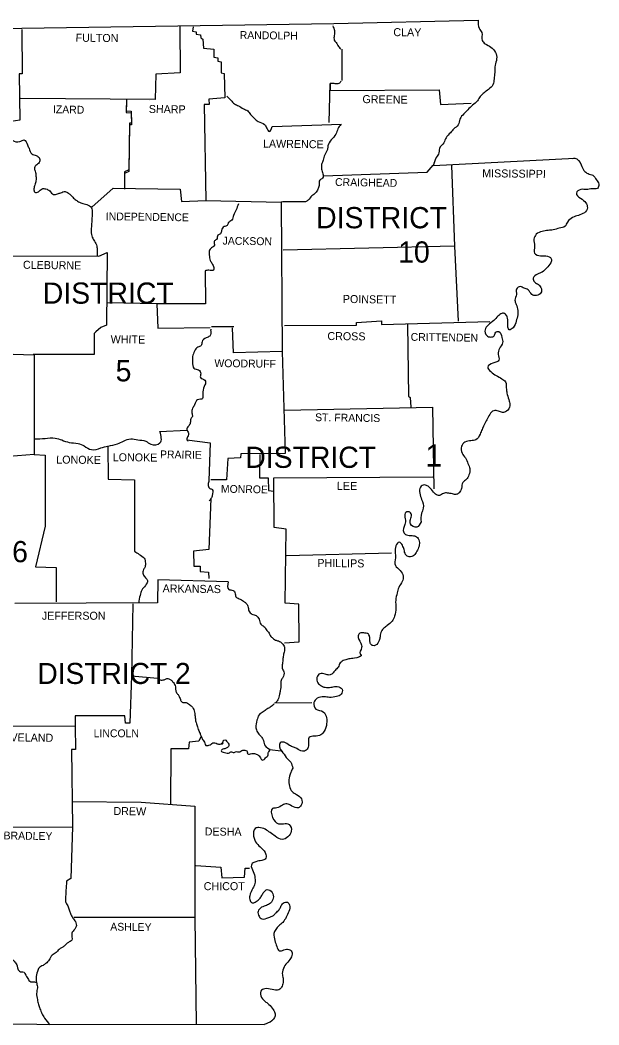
# Model space of a CAD drawing. Extents: x -17668 to 16999, y -17303 to 5867.
# Drawn here: x 2998 to 4708, y 2895 to 5867 of the extents above; entities that cross this region are included whole.
import ezdxf

# ---------------------------------------------------------------- set-up
doc = ezdxf.new("R2010")
doc.units = 0
for name, color, linetype in [('1', 7, 'Continuous'), ('2', 7, 'Continuous'), ('3', 7, 'Continuous')]:
    doc.layers.add(name, color=color, linetype=linetype)

msp = doc.modelspace()

# ---------------------------------------------------------------- linework, layer by layer
at = {"layer": '1'}
for p, q in [((4219.3, 5436.9), (4225.9, 5457.3)), ((4221, 5443.5), (4227.6, 5459.5)), ((3563.3, 4960.3), (3628.8, 4960.3)), ((3749.3, 3847.5), (3859.4, 3849.1))]:
    msp.add_line(p, q, dxfattribs=at)
for points in [[(1332.2, 5841.4), (2222.1, 5840.9), (3003, 5842.5), (3924.3, 5856.8), (4351.4, 5866.7)], [(3003, 5839.2), (3004.1, 5708.2), (2994.8, 5707.7), (2996.4, 5570.7), (2957.9, 5565.2), (2961.2, 5528.3), (2974.4, 5511.2), (2973.3, 5467.7), (2898.5, 5465), (2895.7, 5397.8), (2827.5, 5395.6), (2824.2, 5314.2), (2828, 5307.6), (2829.7, 5177.7), (2947.5, 5170), (2945.8, 4880), (3039.4, 4877.2), (3039.4, 4582.2), (2965.6, 4576.7), (2960.1, 4511.8), (2836.3, 4511.2)], [(3469.2, 5847.5), (3470.3, 5711), (3398.7, 5707.1), (3396.5, 5632.3), (2998.6, 5634.5)], [(3508.8, 5846.9), (3507.2, 5833.7), (3518.2, 5832.1), (3517.6, 5825.5), (3530.3, 5822.7), (3531.4, 5813.9), (3537.4, 5810.1), (3539.1, 5783.6), (3570.5, 5780.3), (3570.5, 5756.7), (3582, 5755), (3582, 5745.7), (3591.9, 5742.9), (3591.4, 5711), (3600.2, 5709.3), (3602.4, 5637.2), (3555.6, 5632.8), (3556.1, 5617.4), (3541.8, 5616.9), (3546.8, 5332.9), (3768.6, 5327.9), (3772.4, 4886.6), (3627.7, 4882.7), (3624.9, 4957)], [(3948.5, 5780.9), (3948.5, 5687.9)], [(3911.1, 5564.1), (3913.9, 5679.1), (3913.9, 5658.7), (4235.8, 5660.4), (4240.2, 5617.4), (4331, 5620.7)], [(3311.8, 5630.6), (3310.7, 5598.7), (3326.1, 5597.6), (3326.6, 5562.4), (3321.1, 5562.4), (3318.9, 5423.7), (3306.3, 5418.2), (3306.3, 5372)], [(3311.8, 5625.7), (3310.7, 5593.8), (3326.1, 5592.7), (3326.6, 5557.4), (3321.1, 5557.4), (3318.9, 5418.8), (3306.3, 5413.3), (3306.3, 5367)], [(3380.6, 5629.5), (3381.1, 5630.1)], [(3742.7, 5551.9), (3946.9, 5559.1)], [(4219.3, 5436.9), (4637, 5458.4)], [(3894.6, 5406.7), (4200.1, 5416.6), (4218.2, 5437.5)], [(4272.2, 5436.4), (4281.5, 5198.1), (4292.5, 4976.3)], [(3209.4, 5313.1), (3272.2, 5369.8), (3470.3, 5367), (3474.1, 5330.2), (3546.2, 5332.9)], [(3840.7, 5329.1), (3773.5, 5329.1), (3768.6, 5327.9)], [(2947.5, 5170), (3230.3, 5168.3), (3254.6, 5179.9), (3252.9, 4964.7), (3236.4, 4957.6), (3221.5, 4944.9), (3216.6, 4940), (3216, 4878.3), (3036.1, 4878.3)], [(4281.5, 5198.1), (3774.6, 5186.5)], [(3544, 5124.9), (3545.1, 5028), (3402, 5027.5), (3255.1, 5030.2)], [(3402, 5027.5), (3404.2, 4955.4), (3558.9, 4958.1)], [(3779, 4963.6), (3991.5, 4964.7), (3992, 4972.4), (4065.8, 4977.9), (4065.8, 4966.4), (4386.1, 4975.2)], [(4142.8, 4966.4), (4145.6, 4754.5), (4150.5, 4751.2), (4152.2, 4722.6)], [(3563.3, 4951), (3560.5, 4950.4)], [(3772.4, 4886.6), (3780.7, 4585), (3649.7, 4584.4), (3649.2, 4572.3), (3611.2, 4570.1), (3607.9, 4507.4), (3561.6, 4507.4)], [(3779, 4713.2), (4216, 4722)], [(4216, 4722), (4220.4, 4481)], [(3410.9, 4650.5), (3490.7, 4654.3)], [(3256.8, 4607.5), (3257.9, 4509), (3335.5, 4507.4), (3336, 4296)], [(3490.7, 4625.7), (3559.4, 4616.9), (3555.6, 4504.6)], [(3039.4, 4582.2), (3071.3, 4580), (3071.8, 4369.8), (3043.2, 4250.4), (3104.3, 4247.6), (3103.8, 4146.3)], [(3705.8, 4581.7), (3705.3, 4513.4), (3730.6, 4513.4), (3731.7, 4475.5), (3747.7, 4473.8)], [(3779, 4025.3), (3822, 4028), (3821.4, 4139.7), (3781.2, 4142.5), (3783.4, 4361), (3748.8, 4365.9), (3747.7, 4512.9), (4217.1, 4516.2)], [(3561.6, 4451.8), (3555, 4301), (3509.9, 4296), (3511, 4251.5), (3529.2, 4252), (3529.7, 4236.6), (3554.5, 4233.8), (3555, 4215.7)], [(3784.5, 4283.4), (4094.9, 4291.1)], [(3612.3, 4205.8), (3404.2, 4211.3), (3403.1, 4143.6), (2982.1, 4141.9)], [(3331, 4140.3), (3326.6, 3927.3), (3403.1, 3921.2)], [(3326.6, 3927.3), (3321.7, 3787.5), (3309, 3787.5), (3306.8, 3809), (3160.4, 3809), (3160.4, 3778.2)], [(2964.5, 3779.8), (3159.3, 3778.7)], [(3160.4, 3778.7), (3161, 3709.9), (3149.4, 3709.4), (3152.7, 3481)], [(3532.5, 3749.5), (3525.9, 3734.7), (3496.7, 3731.9), (3495.1, 3712.1), (3442.8, 3712.1), (3442.2, 3547.6)], [(3594.1, 3725.3), (3595.8, 3727), (3597.4, 3728.6), (3597.4, 3728.6)], [(3151.1, 3555.8), (3355.3, 3554.2), (3513.8, 3542.1)], [(3513.8, 3542.1), (3513.8, 3212.9), (3518.2, 2896.5)], [(2904, 3480.4), (3152.7, 3481)], [(3152.7, 3481), (3147.2, 3328), (3135.1, 3320.3)], [(3516.5, 3366.5), (3590.3, 3362.1), (3593.6, 3330.2), (3660.2, 3332.4), (3662.9, 3359.3), (3675.6, 3359.3)], [(1700.9, 3345), (1702, 2899.8), (3719, 2896.5)], [(3156, 3213.5), (3513.8, 3213.5)]]:
    msp.add_lwpolyline(points, dxfattribs=at)
for points in [[(4351.4, 5866.7), (4354.2, 5842.5), (4361.9, 5829.9), (4363, 5806.8), (4372.3, 5796.9), (4388.3, 5786.9), (4402.6, 5771), (4405.9, 5752.3), (4401.5, 5733), (4400.4, 5711.5), (4398.2, 5692.8), (4394.9, 5675.8), (4381.7, 5662), (4369, 5652.1), (4357.5, 5640.6), (4349.2, 5628.4), (4334.9, 5615.2), (4320.6, 5601.5), (4309, 5589.4), (4297.5, 5574), (4292, 5556.9), (4279.3, 5544.8), (4269.4, 5533.8), (4256.2, 5518.9), (4249.6, 5504.1), (4236.9, 5487), (4234.2, 5470.5), (4225.9, 5457.3), (4225.4, 5455.1)], [(3921.6, 5849.7), (3926.5, 5835.9), (3926, 5821.1), (3926, 5807.3), (3933.1, 5798), (3940.3, 5786.4), (3945.8, 5781.4)], [(3946.3, 5686.2), (3939.2, 5679.1), (3925.4, 5679.1), (3913.9, 5679.1)], [(3608.4, 5642.2), (3620.5, 5629.5), (3631, 5619.1), (3643.1, 5613), (3657.4, 5604.8), (3670.1, 5598.2), (3678.3, 5587.7), (3689.9, 5576.2), (3701.4, 5566.8), (3719.6, 5558), (3725.7, 5548.6), (3733.9, 5537.1), (3742.7, 5551.9)], [(3945.2, 5558.5), (3937, 5545.3), (3930.4, 5529.9), (3917.2, 5512.3), (3907.3, 5495.3), (3905.6, 5483.7), (3897.9, 5468.3), (3893.5, 5452.9), (3888.6, 5439.7), (3888.6, 5425.9), (3892.4, 5412.2), (3891.3, 5399.5), (3883.1, 5393.4), (3880.9, 5377.5), (3877.6, 5366.5), (3870.4, 5355.5), (3859.9, 5347.2), (3848.9, 5334.6), (3840.7, 5329.1)], [(2974.4, 5511.2), (2996.4, 5507.4), (3009.6, 5512.3), (3019, 5498), (3024, 5487), (3032.2, 5471), (3045.4, 5466.1), (3055.3, 5457.3), (3055.3, 5447.9), (3046.5, 5439.1), (3039.9, 5430.3), (3042.1, 5419.9), (3044.3, 5405.5), (3044.3, 5391.8), (3041, 5379.1), (3038.3, 5367.6), (3041, 5357.7), (3051.5, 5359.3), (3062.5, 5367.6), (3074, 5367.6), (3085, 5361.5), (3096.6, 5351.1), (3108.2, 5353.3), (3117.5, 5356), (3130.7, 5359.9), (3140.1, 5354.9), (3148.3, 5348.3), (3158.2, 5337.9), (3167.6, 5331.3), (3179.7, 5325.2), (3194.6, 5321.3), (3208.3, 5312), (3210.5, 5296), (3210, 5282.3), (3208.9, 5265.2), (3207.8, 5246.5), (3209.4, 5228.3), (3215.5, 5216.2), (3223.2, 5201.9), (3225.4, 5188.7), (3224.8, 5167.8)], [(4631, 5457.8), (4637, 5458.4), (4655.8, 5438.6), (4664, 5422.1), (4676.1, 5412.7), (4689.9, 5407.8), (4700.3, 5395.1), (4707.5, 5381.3), (4703.6, 5369.2), (4688.2, 5368.1), (4671.2, 5365.4), (4654.7, 5365.9), (4641.4, 5354.9), (4653.5, 5340.1), (4669.5, 5326.3), (4673.9, 5311.4), (4665.1, 5297.1), (4647.5, 5289.4), (4630.4, 5282.8), (4615, 5269.6), (4607.9, 5257), (4590.8, 5251.5), (4573.2, 5246.5), (4557.8, 5244.8), (4540.2, 5241.5), (4523.1, 5233.3), (4516, 5219), (4518.2, 5198.6), (4517.6, 5177.2), (4535.8, 5170), (4551.7, 5169.4), (4567.1, 5161.2), (4565.5, 5149.1), (4553.9, 5133.7), (4540.2, 5121.6), (4526.4, 5115.5), (4513.8, 5104), (4518.2, 5092.4), (4529.7, 5084.7), (4538, 5072), (4536.9, 5060.5), (4523.7, 5052.2), (4509.4, 5055.5), (4498.9, 5069.3), (4486.8, 5073.7), (4476.3, 5078.6), (4464.2, 5071.5), (4464.2, 5055.5), (4459.8, 5038.5), (4463.7, 5025.8), (4468.6, 5008.2), (4468.1, 4995), (4463.7, 4976.3), (4454.3, 4957), (4443.3, 4951), (4438.9, 4971.9), (4436.7, 4988.9), (4430.1, 4998.8), (4421.3, 4999.4), (4409.7, 4991.1), (4397.1, 4978.5), (4381.1, 4964.7), (4371.8, 4951), (4376.7, 4933.9), (4388.8, 4929.5), (4398.2, 4932.8), (4403.1, 4943.8), (4412.5, 4945.5), (4421.3, 4928.4)], [(3642.5, 5323), (3635.9, 5305.9), (3628.2, 5289.4), (3623.3, 5275.1), (3612.8, 5266.9), (3609.5, 5259.2), (3600.2, 5255.9), (3593, 5244.8), (3589.7, 5234.9), (3582, 5230.5), (3578.2, 5218.4), (3571, 5211.8), (3571.6, 5200.8), (3563.3, 5193.1), (3556.7, 5184.3), (3556.7, 5172.2), (3559.4, 5156.2), (3564.9, 5146.9), (3569.9, 5134.8), (3569.4, 5127.1), (3555.6, 5127.1), (3544, 5124.9)], [(3560.5, 4950.4), (3557.8, 4932.2), (3547.3, 4927.3), (3535.2, 4915.2), (3532.5, 4904.2), (3522.6, 4899.8), (3513.2, 4888.2), (3507.2, 4872.3), (3507.2, 4855.7), (3511, 4837), (3524.8, 4832.1), (3531.4, 4821.1), (3530.3, 4809.5), (3543.5, 4801.8), (3545.7, 4795.2), (3543.5, 4788.1), (3537.4, 4767.7), (3538, 4753.9), (3536.9, 4747.9), (3522, 4744), (3513.2, 4729.2), (3507.2, 4718.7), (3505, 4704.9), (3506.6, 4695), (3502.2, 4687.3), (3500.6, 4675.8), (3495.1, 4665.9), (3490.1, 4656.5), (3495.6, 4645.5), (3494, 4637.8), (3490.7, 4625.7), (3493.4, 4621.8)], [(4421.3, 4928.4), (4423.5, 4912.4), (4414.1, 4895.4), (4410.8, 4878.3), (4412.5, 4861.2), (4394.9, 4851.9), (4379.5, 4840.9), (4388.3, 4827.7), (4404.8, 4815.6), (4421.3, 4806.2), (4431.8, 4796.9), (4434.5, 4774.3), (4437.3, 4760), (4442.8, 4740.2), (4445, 4726.4), (4435.1, 4709.9), (4423.5, 4706.6), (4411.4, 4710.5), (4397.1, 4711.6), (4385.5, 4700.5), (4377.3, 4685.1), (4369, 4669.7), (4363, 4656.5), (4356.9, 4642.2), (4344.8, 4625.7), (4329.9, 4622.9), (4312.3, 4618.5), (4301.9, 4606.4), (4303.5, 4586.1), (4313.4, 4572.3), (4321.1, 4555.3), (4326.6, 4540.4), (4323.9, 4521.7), (4316.2, 4507.9), (4306.3, 4499.7), (4301.9, 4482.1), (4294.7, 4468.8), (4288.1, 4464.4), (4274.9, 4465.5), (4260.6, 4468.3), (4248.5, 4467.2), (4236.9, 4461.1), (4225.4, 4465), (4213.3, 4478.2), (4203.4, 4488.1), (4192.4, 4492), (4180.8, 4485.9), (4178.6, 4467.7), (4184.1, 4449), (4189.1, 4423.7), (4184.1, 4408.3), (4182.4, 4383)], [(3040.5, 4628.5), (3071.3, 4629.6), (3101.6, 4630.7), (3120.8, 4625.1), (3142.8, 4618), (3168.7, 4614.7), (3186.9, 4607.5), (3208.3, 4596.5), (3235.8, 4601.5), (3257.3, 4607), (3285.4, 4614.1), (3303.5, 4621.8), (3324.4, 4628.5), (3345.4, 4625.7), (3369, 4621.3), (3383.9, 4612.5), (3410.9, 4616.3), (3410.9, 4650.5)], [(3555.6, 4504.6), (3553.4, 4493.6), (3557.8, 4482.1), (3565.5, 4478.2), (3566.6, 4467.2), (3563.8, 4456.2), (3561.6, 4451.8), (3556.7, 4445.2)], [(4182.4, 4383), (4169.8, 4367), (4151.1, 4376.9), (4151.1, 4390.1), (4153.8, 4403.9), (4147.2, 4412.7), (4135.7, 4408.9), (4135.7, 4391.8), (4134.6, 4375.3), (4131.3, 4351.6), (4139, 4344.5), (4156.6, 4342.3), (4169.2, 4339), (4176.9, 4326.3), (4176.4, 4310.9), (4170.3, 4296), (4161.5, 4283.9), (4147.8, 4279.5), (4136.8, 4286.7), (4132.4, 4301), (4127.4, 4313.6), (4118.1, 4323), (4108.1, 4312.5), (4105.9, 4293.3), (4106.5, 4276.8), (4106.5, 4254.2), (4120.8, 4239.3), (4129.6, 4222.3), (4126.9, 4206.9), (4116.4, 4188.7), (4112, 4172.8), (4107.6, 4151.3), (4108.1, 4127.6), (4104.3, 4104.5), (4096.6, 4089.1), (4082.3, 4076.4), (4072.9, 4068.2), (4065.2, 4059.9), (4061.4, 4043.4), (4058.6, 4031.9), (4048.2, 4018.1), (4039.9, 4017), (4033.3, 4022.5), (4031.1, 4031.9), (4031.1, 4041.2), (4026.7, 4050.6), (4012.9, 4054.4), (4001.9, 4053.9), (3997, 4046.2), (4004.1, 4024.7), (4006.9, 4011), (4003, 3992.2), (4005.2, 3990), (3985.4, 3979.6), (3969.5, 3977.9), (3956.3, 3974.1), (3943.6, 3965.8), (3937.5, 3953.7), (3928.7, 3943.8), (3921, 3934.5), (3910.6, 3930.1), (3899, 3932.3), (3883.6, 3933.9), (3874.8, 3922.9), (3877.6, 3906.9), (3888, 3897.6), (3903.4, 3893.2), (3919.4, 3894.3), (3934.8, 3895.9), (3949.1, 3888.2), (3946.3, 3873.4), (3932.6, 3866.2), (3912.2, 3864), (3895.7, 3865.7), (3875.9, 3861.3), (3866, 3848.6), (3871.5, 3829.3), (3893, 3821.6), (3902.9, 3803.5), (3903.4, 3786.4), (3896.3, 3763.8), (3886.4, 3753.4), (3867.1, 3749), (3852.2, 3746.2), (3850, 3720.9), (3843.4, 3708.3), (3831.9, 3704.4), (3815.4, 3712.7), (3805.5, 3716.5), (3793.3, 3722), (3777.9, 3731.4), (3766.4, 3729.7), (3769.7, 3705.5), (3770.8, 3704.4), (3784, 3686.2), (3797.2, 3671.9), (3803.3, 3654.9)], [(3336, 4296), (3349.8, 4286.7), (3364.1, 4275.7), (3367.9, 4260.8), (3366.8, 4250.4), (3362.4, 4241.6), (3361.3, 4227.8), (3367.9, 4217.9), (3374, 4209.6), (3367.9, 4194.8), (3357.5, 4181), (3352, 4165.6), (3348.1, 4142.5)], [(3612.3, 4205.8), (3613.9, 4183.2), (3627.1, 4179.9), (3632.6, 4173.9), (3635.4, 4161.2), (3644.8, 4155.7), (3657.4, 4148), (3665.1, 4142.5), (3670.6, 4133.7), (3673.9, 4119.4), (3682.7, 4110), (3694.8, 4105.6), (3703.6, 4095.2), (3709.1, 4080.3), (3717.9, 4073.7), (3726.8, 4062.1), (3731.2, 4057.2), (3738.9, 4044), (3746.6, 4037.4), (3752.1, 4033.5), (3760.9, 4030.8), (3771.9, 4023.6), (3779, 4012.6), (3779, 4004.3), (3776.3, 3991.7), (3774.1, 3978.5), (3773, 3963.6), (3771.9, 3950.4), (3776.8, 3939.4), (3774.1, 3922.9), (3768.6, 3914.1), (3768, 3902), (3766.4, 3883.8), (3764.2, 3873.4), (3759.2, 3856.3), (3752.1, 3847.5)], [(3403.1, 3921.2), (3411.4, 3915.7), (3423, 3916.3), (3430.7, 3919.6), (3436.7, 3919), (3445, 3914.1), (3450.5, 3907.5), (3454.3, 3902.5), (3457.1, 3894.8), (3457.1, 3887.7), (3459.8, 3877.8), (3463.1, 3873.9), (3467.5, 3866.8), (3470.3, 3860.2), (3471.9, 3855.8), (3478, 3848.6), (3483.5, 3849.1), (3488.5, 3848.6), (3495.1, 3844.7), (3505, 3837), (3506.6, 3834.8), (3513.2, 3820.5), (3514.3, 3811.7), (3515.4, 3800.2), (3517.6, 3789.2), (3522, 3777.1), (3524.2, 3768.8), (3529.2, 3757.2), (3532.5, 3749.5), (3536.9, 3739.6), (3543.5, 3728.6), (3546.2, 3722), (3555.6, 3722.6), (3562.2, 3725.3), (3567.2, 3729.7), (3573.2, 3729.2), (3579.8, 3727), (3588.6, 3725.3), (3594.1, 3728.6), (3596.9, 3730.8), (3597.4, 3735.8), (3602.4, 3738.5), (3607.9, 3734.7), (3613.9, 3725.9), (3613.9, 3720.4), (3611.7, 3717.1), (3604.6, 3712.7), (3594.7, 3709.4), (3591.9, 3705.5), (3601.3, 3701.1), (3616.1, 3700), (3620, 3703.3), (3629.9, 3700.6), (3633.7, 3703.3), (3647, 3702.8), (3653, 3707.2), (3665.1, 3706.6), (3669, 3703.9), (3669, 3698.9), (3678.9, 3696.7), (3686, 3698.4), (3695.4, 3695.6), (3703.6, 3691.2), (3708, 3685.1), (3713.5, 3678.5), (3718.5, 3680.2), (3722.4, 3685.1), (3730.6, 3693.9), (3730.6, 3699.5), (3732.8, 3703.3), (3735.6, 3708.8)], [(3748.2, 3844.2), (3736.7, 3834.8), (3726.8, 3829.3), (3716.3, 3821.6), (3703.6, 3812.3), (3697.6, 3796.3), (3694.3, 3774.3), (3698.7, 3761.1), (3708.6, 3749.5), (3715.2, 3740.2), (3720.1, 3723.7), (3732.3, 3712.1), (3736.1, 3710.5)], [(3803.3, 3654.9), (3797.7, 3642.2), (3791.7, 3620.2), (3793.3, 3601.5), (3801.6, 3585.5), (3814.8, 3576.7), (3829.1, 3564.1), (3828, 3544.8), (3819.8, 3537.6), (3800.5, 3542.6), (3785.6, 3549.2), (3773, 3545.4), (3755.9, 3537.1), (3743.3, 3535.4), (3743.8, 3509), (3760.9, 3490.3), (3775.7, 3490.3), (3792.8, 3488.1), (3798.9, 3468.3), (3788.9, 3451.8), (3772.4, 3443.5), (3751.5, 3453.4), (3736.7, 3463.9), (3721.8, 3473.8), (3703.1, 3478.8), (3692.6, 3476.6), (3687.7, 3453.4), (3696.5, 3432.5), (3710.8, 3418.2), (3724, 3399.5), (3721.8, 3385.8), (3711.9, 3381.9), (3694.3, 3378), (3683.8, 3372.5), (3681.1, 3368.1), (3686.6, 3349.4), (3691.5, 3329.1), (3691.5, 3313.7), (3685.5, 3299.3), (3676.1, 3277.3), (3677.2, 3263), (3683.8, 3256.4), (3692.1, 3258.6), (3703.1, 3266.3), (3710.2, 3275.1), (3716.3, 3286.1), (3727.9, 3295.5), (3742.2, 3287.2), (3745.5, 3270.2), (3737.2, 3255.3), (3725.7, 3248.7), (3711.3, 3243.2), (3700.9, 3231.1), (3703.6, 3216.8), (3711.9, 3209.1), (3732.3, 3212.9), (3746, 3219), (3753.7, 3226.7), (3763.1, 3236.1), (3768, 3245.4), (3775.2, 3255.3), (3787.8, 3258.1), (3793.9, 3249.8), (3791.7, 3231.1), (3784, 3213.5), (3773.5, 3198.6), (3762, 3188.2), (3747.7, 3165.6), (3750.4, 3144.7), (3755.9, 3127.6), (3763.6, 3114.4), (3776.8, 3117.2), (3791.7, 3118.8), (3800.5, 3111.7), (3799.4, 3096.3), (3788.4, 3081.4), (3777.9, 3067.1), (3772.4, 3047.3), (3774.6, 3033.5), (3774.6, 3020.9), (3770.2, 3007.1), (3762.5, 2999.4), (3742.2, 3000), (3720.7, 3002.2), (3709.1, 2995.6), (3711.3, 2976.8), (3724, 2963.1), (3732.8, 2955.9), (3745.5, 2940.5), (3751, 2927.9), (3749.3, 2916.8), (3741.6, 2907.5), (3719, 2896.5)], [(3135.1, 3320.3), (3133.5, 3303.2), (3132.9, 3287.2), (3131.8, 3271.8), (3131.8, 3260.3), (3138.4, 3247.6), (3142.3, 3235.5), (3146.1, 3225), (3153.8, 3211.3), (3161, 3200.8), (3163.2, 3186), (3158.8, 3178.3), (3150.5, 3166.7), (3150, 3145.8), (3140.1, 3139.2), (3127.4, 3128.2), (3120.3, 3123.2), (3112.6, 3118.3), (3104.3, 3109.5), (3092.2, 3101.2), (3083.4, 3087.5), (3073.5, 3077), (3065.2, 3071.5), (3053.7, 3064.3), (3048.7, 3053.3), (3044.9, 3033), (3046.5, 3018.1), (3048.7, 3004.9), (3046, 2988.4), (3048.7, 2970.2), (3051.5, 2955.9), (3055.9, 2943.3), (3061.9, 2929), (3069.6, 2915.7), (3086.1, 2895.4)], [(2586.4, 3193.1), (2595.2, 3199.2), (2603.5, 3202.5), (2611.7, 3200.8), (2620.5, 3199.7), (2628.2, 3200.8), (2638.2, 3199.2), (2646.4, 3194.2), (2655.8, 3190.4), (2665.1, 3190.4), (2673.4, 3190.4), (2680.5, 3185.4), (2693.7, 3186), (2704.7, 3190.4), (2715.8, 3193.7), (2730.6, 3195.3), (2743.8, 3186), (2753.2, 3178.3), (2760.9, 3169.5), (2766.4, 3159.6), (2772.4, 3154.1), (2782.3, 3150.2), (2790.1, 3148.5), (2799.4, 3145.8), (2804.4, 3143.6), (2808.8, 3133.1), (2815.9, 3118.8), (2829.7, 3113.9), (2846.7, 3120.5), (2860.5, 3124.3), (2870.4, 3127.6), (2876.5, 3129.8), (2882, 3130.4), (2880.3, 3131.5), (2886.9, 3133.1), (2893, 3128.7), (2896.8, 3122.7), (2903.4, 3113.9), (2909.5, 3106.2), (2915.5, 3103.4), (2921.6, 3106.7), (2929.8, 3104), (2937, 3101.2), (2945.3, 3099), (2952.4, 3098.5), (2961.8, 3096.3), (2968.9, 3092.4), (2975.5, 3088.6), (2982.1, 3081.4), (2988.7, 3070.4), (2990.9, 3061.6), (2998.6, 3052.8), (3005.8, 3052.8), (3016.2, 3038.5), (3020.1, 3033), (3028.4, 3023.1), (3034.4, 3023.1), (3046, 3020.9)]]:
    msp.add_spline(points, degree=3, dxfattribs=at)
at = {"layer": '3'}
msp.add_line((3734.5, 3709.9), (3769.1, 3705.5), dxfattribs=at)

# ---------------------------------------------------------------- texts
at = {"layer": '1'}
msp.add_text('1', height=66, dxfattribs=at).set_placement((4195.7, 4546.4))
at = {"layer": '2'}
for s, height, rotation, p in [('FULTON', 23.66, 359.4996, (3161.5, 5802.9)), ('RANDOLPH', 23.11, 359.2583, (3646.4, 5811.2)), ('CLAY', 23.66, 359.2258, (4100.4, 5819.4)), ('SHARP', 23.66, 359.3905, (3377.8, 5592.1)), ('GREENE', 23.67, 359.2361, (4009.1, 5621.3)), ('IZARD', 23.11, 358.9258, (3094.4, 5591.6)), ('LAWRENCE', 23.67, 359.2678, (3715.2, 5489.8)), ('MISSISSIPPI', 23.66, 359.3097, (4363, 5402.2)), ('CRAIGHEAD', 23.11, 359.1159, (3928.2, 5376.4)), ('INDEPENDENCE', 23.108, 359.2187, (3250.7, 5275.1)), ('JACKSON', 23.11, 359.1352, (3595.8, 5203)), ('CLEBURNE', 23.66, 359.2535, (3005.8, 5131.5)), ('POINSETT', 23.66, 359.1987, (3951.1, 5030.4)), ('WHITE', 23.67, 359.3139, (3265, 4911.3)), ('CROSS', 23.66, 359.3839, (3905.6, 4920.7)), ('CRITTENDEN', 23.11, 359.213, (4151.6, 4918.5)), ('WOODRUFF', 23.11, 359.2748, (3571.6, 4840.9)), ('ST. FRANCIS', 23.108, 359.2216, (3869.3, 4680.7)), ('LONOKE', 23.67, 359.4974, (3104.3, 4555.3)), ('LONOKE', 23.67, 359.4974, (3271.1, 4562.4)), ('PRAIRIE', 23.11, 359.2116, (3410.9, 4571.2)), ('MONROE', 23.11, 359.0331, (3590.8, 4469.4)), ('LEE', 23.67, 359.4327, (3933.7, 4477.7)), ('PHILLIPS', 23.66, 359.3179, (3875.9, 4249.8)), ('ARKANSAS', 23.66, 359.2678, (3418.6, 4174.4)), ('CLEVELAND', 23.67, 359.3377, (2907.3, 3734.7)), ('DREW', 23.66, 359.2258, (3273.3, 3516.2)), ('DESHA', 23.66, 359.3704, (3542.9, 3455.6)), ('BRADLEY', 23.11, 359.1449, (2948.6, 3444.1)), ('ASHLEY', 23.11, 359.2361, (3263.9, 3174.4))]:
    msp.add_text(s, height=height, rotation=rotation, dxfattribs=at).set_placement(p)
for s, height, p in [('JEFFERSON', 23.67, (3061.9, 4093.5)), ('LINCOLN', 23.11, (3214.9, 3746.2)), ('CHICOT', 23.67, (3540.2, 3293.8))]:
    msp.add_text(s, height=height, dxfattribs=at).set_placement(p)
at = {"layer": '3'}
for s, height, p in [('DISTRICT', 62.74, (3872.3, 5251.1)), ('10', 62.74, (4114.8, 5149.6)), ('DISTRICT', 62.74, (3064.7, 5028)), ('5', 62.7, (3279.9, 4798.5)), ('DISTRICT', 62.74, (3662.9, 4542.6)), ('DISTRICT 6', 62.74, (2563.9, 4263.6)), ('DISTRICT 2', 62.19, (3048.7, 3903.6))]:
    msp.add_text(s, height=height, dxfattribs=at).set_placement(p)

doc.saveas('drawing.dxf')
